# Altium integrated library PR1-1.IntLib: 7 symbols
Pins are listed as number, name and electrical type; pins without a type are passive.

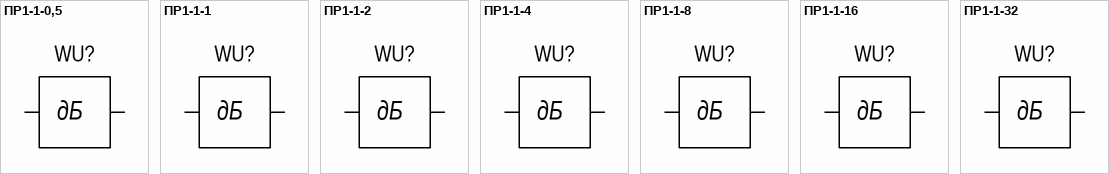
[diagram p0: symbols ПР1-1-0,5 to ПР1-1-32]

## ПР1-1-0,5
designator WU?  (value not drawn)
Поглотитель резистивный малой мощности; ТКС: ±300; Номинальное сопротивление: 50 Ом; Допускаемое отклонение от номинального сопротивления: ±2 %; Диапазон рабочих температур: от -60 до +125 С; Предельная рабочая частота: 18 ГГц; Мощность рассеяния: 0,5 Вт; Минимальная наработка: 20000 час; КСВН в диапазоне до 1,2 ГГц: 1,15; КСВН в диапазоне от 1,2 до 18 ГГц: 1,5; Срок сохраняемости: 15 лет; Ослабление: 0,5 дБ
footprint PR1-1-0.5 (Поглотитель резистивный малой мощности АО"НПО"ЭРКОН")
footprint PR1-1-0.5 V2 (Поглотитель резистивный малой мощности АО"НПО"ЭРКОН")
pins: 1, 2

## ПР1-1-1
designator WU?  (value not drawn)
Поглотитель резистивный малой мощности; ТКС: ±300; Номинальное сопротивление: 50 Ом; Допускаемое отклонение от номинального сопротивления: ±2 %; Диапазон рабочих температур: от -60 до +125 С; Предельная рабочая частота: 18 ГГц; Мощность рассеяния: 0,5 Вт; Минимальная наработка: 20000 час; КСВН в диапазоне до 1,2 ГГц: 1,15; КСВН в диапазоне от 1,2 до 18 ГГц: 1,5; Срок сохраняемости: 15 лет; Ослабление: 1 дБ
footprint PR1-1-1 (Поглотитель резистивный малой мощности АО"НПО"ЭРКОН")
footprint PR1-1-1 V2 (Поглотитель резистивный малой мощности АО"НПО"ЭРКОН")
pins: 1, 2

## ПР1-1-2
designator WU?  (value not drawn)
Поглотитель резистивный малой мощности; ТКС: ±300; Номинальное сопротивление: 50 Ом; Допускаемое отклонение от номинального сопротивления: ±2 %; Диапазон рабочих температур: от -60 до +125 С; Предельная рабочая частота: 18 ГГц; Мощность рассеяния: 0,5 Вт; Минимальная наработка: 20000 час; КСВН в диапазоне до 1,2 ГГц: 1,15; КСВН в диапазоне от 1,2 до 18 ГГц: 1,5; Срок сохраняемости: 15 лет; Ослабление: 2 дБ
footprint PR1-1-2 (Поглотитель резистивный малой мощности АО"НПО"ЭРКОН")
footprint PR1-1-2 V2 (Поглотитель резистивный малой мощности АО"НПО"ЭРКОН")
pins: 1, 2

## ПР1-1-4
designator WU?  (value not drawn)
Поглотитель резистивный малой мощности; ТКС: ±300; Номинальное сопротивление: 50 Ом; Допускаемое отклонение от номинального сопротивления: ±2 %; Диапазон рабочих температур: от -60 до +125 С; Предельная рабочая частота: 18 ГГц; Мощность рассеяния: 0,5 Вт; Минимальная наработка: 20000 час; КСВН в диапазоне до 1,2 ГГц: 1,15; КСВН в диапазоне от 1,2 до 18 ГГц: 1,5; Срок сохраняемости: 15 лет; Ослабление: 4 дБ
footprint PR1-1-4 (Поглотитель резистивный малой мощности АО"НПО"ЭРКОН")
footprint PR1-1-4 V2 (Поглотитель резистивный малой мощности АО"НПО"ЭРКОН")
pins: 1, 2

## ПР1-1-8
designator WU?  (value not drawn)
Поглотитель резистивный малой мощности; ТКС: ±300; Номинальное сопротивление: 50 Ом; Допускаемое отклонение от номинального сопротивления: ±2 %; Диапазон рабочих температур: от -60 до +125 С; Предельная рабочая частота: 18 ГГц; Мощность рассеяния: 0,5 Вт; Минимальная наработка: 20000 час; КСВН в диапазоне до 1,2 ГГц: 1,15; КСВН в диапазоне от 1,2 до 18 ГГц: 1,5; Срок сохраняемости: 15 лет; Ослабление: 8 дБ
footprint PR1-1-8 (Поглотитель резистивный малой мощности АО"НПО"ЭРКОН")
footprint PR1-1-8 V2 (Поглотитель резистивный малой мощности АО"НПО"ЭРКОН")
pins: 1, 2

## ПР1-1-16
designator WU?  (value not drawn)
Поглотитель резистивный малой мощности; ТКС: ±300; Номинальное сопротивление: 50 Ом; Допускаемое отклонение от номинального сопротивления: ±2 %; Диапазон рабочих температур: от -60 до +125 С; Предельная рабочая частота: 18 ГГц; Мощность рассеяния: 0,5 Вт; Минимальная наработка: 20000 час; КСВН в диапазоне до 1,2 ГГц: 1,15; КСВН в диапазоне от 1,2 до 18 ГГц: 1,5; Срок сохраняемости: 15 лет; Ослабление: 8 дБ
footprint PR1-1-16 (Поглотитель резистивный малой мощности АО"НПО"ЭРКОН")
footprint PR1-1-16 V2 (Поглотитель резистивный малой мощности АО"НПО"ЭРКОН")
pins: 1, 2

## ПР1-1-32
designator WU?  (value not drawn)
Поглотитель резистивный малой мощности; ТКС: ±300; Номинальное сопротивление: 50 Ом; Допускаемое отклонение от номинального сопротивления: ±2 %; Диапазон рабочих температур: от -60 до +125 С; Предельная рабочая частота: 18 ГГц; Мощность рассеяния: 0,5 Вт; Минимальная наработка: 20000 час; КСВН в диапазоне до 1,2 ГГц: 1,15; КСВН в диапазоне от 1,2 до 18 ГГц: 1,5; Срок сохраняемости: 15 лет; Ослабление: 32 дБ
footprint PR1-1-32 (Поглотитель резистивный малой мощности АО"НПО"ЭРКОН")
footprint PR1-1-32 V2 (Поглотитель резистивный малой мощности АО"НПО"ЭРКОН")
pins: 1, 2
